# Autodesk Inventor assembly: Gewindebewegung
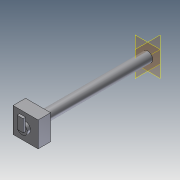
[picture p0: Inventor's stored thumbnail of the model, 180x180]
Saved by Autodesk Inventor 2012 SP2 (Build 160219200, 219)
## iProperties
Company: Caverion Deutschland GmbH - Krantz Komponenten
Created: 2013-10
Part Number: Gewindebewegung
Document SubType Name: Assembly
Designer: Wsommer
Mass: 8.61851 g
Surface Area: 44.7947 cm^2
Volume: 8.61851 cm^3
Density: 1 g/cm^3
Author: Wsommer
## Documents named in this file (3)
- D:\Support\2012\CAD.DE\Bewegung\Gewindebewegung.iam
- D:\Support\2012\CAD.DE\Bewegung\Innengewinde.ipt
- D:\Support\2012\CAD.DE\Bewegung\Aussengewindestange.ipt
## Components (2 placed, 2 different names)
1. Innengewinde:1 — Auf Wellenachse platzieren, Gegen Verdrehung sichern, Drehung/Translation:1
2. Aussengewindestange:1 — Wellenachse fixieren, Wellenende fixieren, Drehwinkel - Bitte hier animieren, Auf Wellenachse platzieren, Drehung/Translation:1
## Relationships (6: Mate 3, Angle 2, RelateRotateTranslate 1)
- Wellenachse fixieren [Mate]: Aussengewindestange:1
- Wellenende fixieren [Mate]: Aussengewindestange:1
- Drehwinkel - Bitte hier animieren [Angle]: Aussengewindestange:1
- Auf Wellenachse platzieren [Mate]: Innengewinde:1 ↔ Aussengewindestange:1
- Gegen Verdrehung sichern [Angle]: Innengewinde:1
- Drehung/Translation:1 [RelateRotateTranslate]: Innengewinde:1 ↔ Aussengewindestange:1
